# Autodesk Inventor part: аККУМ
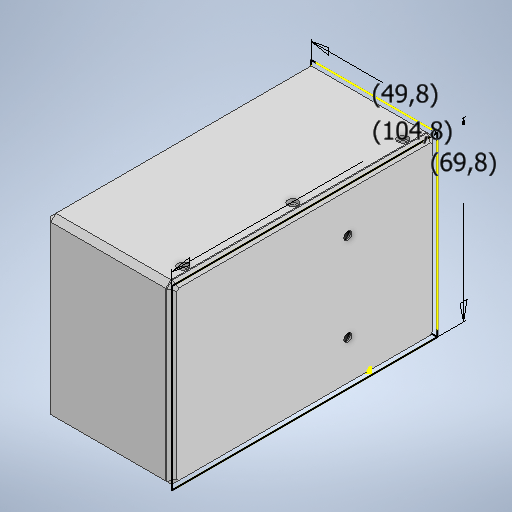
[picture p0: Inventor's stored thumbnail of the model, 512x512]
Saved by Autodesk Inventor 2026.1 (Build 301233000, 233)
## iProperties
Created: 2026-01
Part Number: аККУМ
Material: Типовые
Document SubType Name: Modeling
Designer: Yury Melnikov
Density: 1 g/cm^3
Appearance: По умолчанию
Author: Yury Melnikov
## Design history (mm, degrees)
sketch "Эскиз1"
  geometry: L1 (0, 0)-(65, 0); L2 (65, 0)-(65, 75); L3 (65, 75)-(0, 75); L4 (0, 75)-(0, 0); L5 (65, 0)-(0, 0); L6 (0, 0)-(0, -25); L7 (0, -25)-(65, -25); L8 (65, -25)-(65, 0); 1 further point
  constraints: 16 end point, 4 parallel, 2 horizontal, 2 perpendicular, 1 collinear
  dimensions: "d0" = 75 distance of L1.end L2.end; "d1" = 65 distance of L2.end L3.end; "d4" = 25 distance of L6.end L5.end
extrude "Выдавливание1" new body sketch "Эскиз1" distance "d2" = 45; taper "d3" = 0 deg
feature "Оболочка1" dims "d5" = 2.4
chamfer "Фаска1" distance "d9" = 2; stored, may be unused: second distance "d10" = 2, angle "d11" = 45 deg
sketch "Эскиз3"
  geometry: L1 (25, 63)-(25, 2) reference; L2 (23, 0)-(25, 2) reference; L3 (23, 0)-(-73, 0) reference; L4 (-75, 2)-(-73, 0) reference; L5 (-75, 2)-(-75, 63) reference; L6 (-73, 65)-(-75, 63) reference; L7 (-73, 65)-(23, 65) reference; L8 (25, 63)-(23, 65) reference; L9 (-75.4, -2.4)-(-77.4, -0.4) reference; L10 (-75.4, -2.4)-(25.4, -2.4) reference; L11 (27.4, -0.4)-(25.4, -2.4) reference; L12 (27.4, -0.4)-(27.4, 65.4) reference; L13 (25.4, 67.4)-(27.4, 65.4) reference; L14 (25.4, 67.4)-(-75.4, 67.4) reference; L15 (-77.4, 65.4)-(-75.4, 67.4) reference; L16 (-77.4, 65.4)-(-77.4, -0.4) reference; L17 (-72.917, 0.2)-(22.917, 0.2); L18 (22.917, 0.2)-(24.8, 2.083); L19 (24.8, 2.083)-(24.8, 62.917); L20 (24.8, 62.917)-(22.917, 64.8); L21 (22.917, 64.8)-(-72.917, 64.8); L22 (-72.917, 64.8)-(-74.8, 62.917); L23 (-74.8, 62.917)-(-74.8, 2.083); L24 (-74.8, 2.083)-(-72.917, 0.2); L25 (22.089, 2.2)-(-72.089, 2.2); L26 (-72.089, 2.2)-(-72.8, 2.911); L27 (-72.8, 2.911)-(-72.8, 62.089); L28 (-72.8, 62.089)-(-72.089, 62.8); L29 (-72.089, 62.8)-(22.089, 62.8); L30 (22.089, 62.8)-(22.8, 62.089); L31 (22.8, 62.089)-(22.8, 2.911); L32 (22.8, 2.911)-(22.089, 2.2); 1 further point
  constraints: 32 end point, 14 other
  dimensions: "d12" = 0.2 distance between parallel lines of L3 L17; "d13" = 2 distance between parallel lines of L17 L25
extrude "Выдавливание3" new body sketch "Эскиз3" distance "d14" = 5; taper "d15" = 0 deg
sketch "Эскиз4"
  geometry: L1 (25, 63)-(25, 2) reference; L2 (23, 0)-(25, 2) reference; L3 (23, 0)-(-73, 0) reference; L4 (-75, 2)-(-73, 0) reference; L5 (-75, 2)-(-75, 63) reference; L6 (-73, 65)-(-75, 63) reference; L7 (-73, 65)-(23, 65) reference; L8 (25, 63)-(23, 65) reference; L9 (-75.4, -2.4)-(-77.4, -0.4) reference; L10 (-75.4, -2.4)-(25.4, -2.4) reference; L11 (27.4, -0.4)-(25.4, -2.4) reference; L12 (27.4, -0.4)-(27.4, 65.4) reference; L13 (25.4, 67.4)-(27.4, 65.4) reference; L14 (25.4, 67.4)-(-75.4, 67.4) reference; L15 (-77.4, 65.4)-(-75.4, 67.4) reference; L16 (-77.4, 65.4)-(-77.4, -0.4) reference; 1 further point
extrude "Выдавливание4" join sketch "Эскиз4" distance "d16" = 2.4; taper "d17" = 0 deg
chamfer "Фаска2" distance "d18" = 2; stored, may be unused: second distance "d19" = 2, angle "d20" = 45 deg
chamfer "Фаска3" distance "d21" = 1.5; stored, may be unused: second distance "d22" = 2, angle "d23" = 45 deg
chamfer "Фаска4" distance "d24" = 0.5; stored, may be unused: second distance "d25" = 2, angle "d26" = 45 deg
sketch "Эскиз5"
  geometry: L1 (40.9, -98.317)-(40.9, -2.483) reference; L2 (45.4, -98.317)-(40.9, -98.317) reference; L3 (45.4, -2.483)-(45.4, -98.317) reference; L4 (45.4, -2.483)-(40.9, -2.483) reference; L5 (43.15, -93.817)-(43.15, -50.4); L6 (43.15, -50.4)-(43.15, -6.983); C1 r 0.75 at (43.15, -93.817); C2 r 0.75 at (43.15, -50.4); C3 r 0.75 at (43.15, -6.983); 3 further points
  constraints: 4 end point, 3 centre point, 2 collinear, 2 equal radius, 2 midpoint, 1 horizontal alignment, 1 point on line, 1 vertical
  dimensions: "d27" = 1.5 diameter of C2; "d28" = 4.5 distance from line of L2 L5.start
extrude "Выдавливание5" cut sketch "Эскиз5" distance "d29" = 75; taper "d30" = 0 deg
sketch "Эскиз8"
  geometry: L1 (-2.4, -2.4)-(98.4, -2.4) reference; L2 (-2.4, -2.4)-(72.6, -2.4); L3 (72.6, -2.4)-(72.6, 62.6); L4 (72.6, 62.6)-(-2.4, 62.6); L5 (-2.4, 62.6)-(-2.4, -2.4); L6 (74.6, -2.4)-(74.6, 62.6); L7 (72.6, -2.4)-(74.6, -2.4); L8 (72.6, 62.6)-(74.6, 62.6); L9 (74.6, 55.993)-(72.6, 55.993); L10 (72.6, 55.993)-(72.6, 64.22); L11 (72.6, 64.22)-(74.6, 64.22); L12 (74.6, 64.22)-(74.6, 55.993); 3 further points
  constraints: 22 end point, 5 parallel, 4 point on line, 3 horizontal, 2 perpendicular, 1 vertical
  dimensions: "d31" = 65 distance of L2.end L3.end; "d32" = 75 distance between parallel lines of L5 L3; "d33" = 2 distance between parallel lines of L6 L3
extrude "Выдавливание6" join sketch "Эскиз8" distance "d34" = 40; taper "d35" = 0 deg
chamfer "Фаска5" distance "d36" = 1; stored, may be unused: second distance "d37" = 2, angle "d38" = 45 deg
sketch "Эскиз9"
  geometry: L1 (0, 0)-(0, 65.8) reference; L2 (45.4, 0)-(0, 0) reference; L3 (15, 15)-(15, 50.8); C1 r 3 at (15, 15); C2 r 15 at (15, 15); C3 r 6.1 at (15, 50.8); 3 further points
  constraints: 3 centre point, 2 end point, 2 midpoint, 2 tangent, 1 coincident, 1 horizontal alignment, 1 vertical, 1 vertical alignment
  dimensions: "d39" = 6 diameter of C1; "d40" = 30 diameter of C2; "d41" = 12.2 diameter of C3
extrude "Выдавливание7" cut sketch "Эскиз9" distance "d42" = 3; taper "d43" = 0 deg
sketch "Эскиз10"
  geometry: L1 (40.4, -74)-(2.4, -74) reference; L2 (40.4, -74)-(40.4, -78) reference; L3 (2.4, -78)-(40.4, -78) reference; L4 (2.4, -98.4)-(2.4, -78) reference; L5 (45.4, -98.4)-(2.4, -98.4) reference; L6 (45.4, -2.4)-(45.4, -98.4) reference; L7 (2.4, -2.4)-(45.4, -2.4) reference; L8 (2.4, -74)-(2.4, -2.4) reference; L9 (31.65, -83.95)-(16.15, -83.95); L10 (16.15, -83.95)-(16.15, -92.45); L11 (16.15, -92.45)-(31.65, -92.45); L12 (31.65, -92.45)-(31.65, -83.95); C1 r 0.75 at (43.15, -93.817) reference; C2 r 0.75 at (43.15, -50.4) reference; C3 r 0.75 at (43.15, -6.983) reference; 5 further points
  constraints: 8 end point, 4 midpoint, 2 parallel, 1 horizontal, 1 horizontal alignment, 1 perpendicular, 1 vertical alignment
  dimensions: "d44" = 15.5 distance of L11.end L10.end; "d45" = 8.5 distance of L10.end L9.end
extrude "Выдавливание8" cut sketch "Эскиз10" distance "d46" = 3; taper "d47" = 0 deg
chamfer "Фаска6" distance "d48" = 0.7; stored, may be unused: second distance "d49" = 2, angle "d50" = 45 deg
chamfer "Фаска7" distance "d51" = 0.5; stored, may be unused: second distance "d52" = 2, angle "d53" = 45 deg
sketch "Эскиз11"
  geometry: C1 r 0.75 at (43.15, -6.983) reference; C2 r 0.75 at (43.15, -50.4) reference; C3 r 0.75 at (43.15, -93.817) reference; C4 r 2 at (43.15, -6.983); C5 r 2 at (43.15, -50.4); C6 r 2 at (43.15, -93.817); 1 further point
  constraints: 3 centre point, 2 equal radius
  dimensions: "d54" = 4 diameter of C4
extrude "Выдавливание9" cut sketch "Эскиз11" distance "d55" = 1.4; taper "d56" = 0 deg
chamfer "Фаска8" distance "d57" = 0.5; stored, may be unused: second distance "d58" = 2, angle "d59" = 45 deg
node "РабПлоскость2"
mirror "Зеркальное отражение1"
node "РабПлоскость3"
sketch "Эскиз12"
  geometry: L1 (2, 61)-(2, 0) reference; L2 (2, 0)-(2, 61) reference; L3 (2, 9.6)-(2, 15.6) reference; L4 (2, 42.3)-(2, 54.5) reference; L5 (2, 49)-(-4.5, 49); L6 (-4.5, 49)-(-4.5, 42); L7 (-4.5, 42)-(-2.5, 42); L8 (-2.5, 42)-(-2.5, 47); L9 (-2.5, 47)-(2, 47); L10 (-2.5, 47)-(-2.5, 49); L11 (2, 30.5)-(16.292, 30.5); L12 (2, 18.7)-(2, 6.5); L13 (2, 12)-(-4.5, 12); L14 (-4.5, 12)-(-4.5, 19); L15 (-4.5, 19)-(-2.5, 19); L16 (-2.5, 19)-(-2.5, 14); L17 (-2.5, 14)-(2, 14); L18 (-2.5, 14)-(-2.5, 12); 6 further points
  constraints: 28 end point, 9 symmetric about line, 8 point on line, 3 horizontal, 3 perpendicular, 2 midpoint, 1 vertical
  dimensions: "d62" = 5 distance of L7.end L8.end; "d63" = 2 distance of L6.end L7.end; "d64" = 4.5 distance of L8.end L9.end; "d65" = 33 distance from line of L17 point (-0.25, 47)
extrude "Выдавливание10" join sketch "Эскиз12" distance "d66" = 6; taper "d67" = 0 deg
sketch "Эскиз13"
  geometry: L1 (37, 16.4)-(37, 21.4) reference; L2 (37, 21.4)-(31, 21.4) reference; L3 (31, 16.4)-(31, 21.4) reference; L4 (37, 16.4)-(31, 16.4) reference; L5 (37, 44.4)-(37, 49.4) reference; L6 (37, 49.4)-(31, 49.4) reference; L7 (31, 44.4)-(31, 49.4) reference; L8 (37, 44.4)-(31, 44.4) reference; L9 (27.35, 16.65)-(40.65, 16.65); L10 (40.65, 16.65)-(40.65, 49.15); L11 (40.65, 49.15)-(27.35, 49.15); L12 (27.35, 49.15)-(27.35, 16.65); L13 (31, 21.4)-(31, 44.4); C1 r 1.65 at (30.35, 41.15); C2 r 1.65 at (30.35, 36.15); C3 r 1.65 at (30.35, 31.15); C4 r 1.65 at (30.35, 26.15); C5 r 2.1 at (35.65, 41.65); 5 further points
  constraints: 10 end point, 5 centre point, 4 midpoint, 2 parallel, 2 vertical, 1 horizontal, 1 horizontal alignment, 1 perpendicular, 1 vertical alignment, 6 other
  dimensions: "d68" = 32.5 distance of L11.end L9.start; "d69" = 13.3 distance of L9.start L9.end; "d70" = 3 horizontal distance of C1.centre L11.end; "d71" = 8 vertical distance of L11.end C1.centre; "d72" = 3.3 diameter of C1; "d75" = 5 distance of C1.centre C2.centre; "d80" = 4.2 diameter of C5; "d81" = 7.5 vertical distance of L10.end C5.centre; "d82" = 5 distance from line of L10 C5.centre
extrude "Выдавливание11" cut sketch "Эскиз13" distance "d83" = 6; taper "d84" = 0 deg
chamfer "Фаска9" distance "d85" = 0.5; stored, may be unused: second distance "d86" = 2, angle "d87" = 45 deg
chamfer "Фаска10" distance "d88" = 3; stored, may be unused: second distance "d89" = 2, angle "d90" = 45 deg
sketch "Эскиз14"
  geometry: L1 (-77.4, 65.4)-(-77.4, -0.4) reference; L2 (-7.94, 49.9)-(-7.94, 15.1); L3 (25.4, 64.572)-(25.4, 0.428) reference; C1 r 1.6 at (-7.94, 49.9); C2 r 1.6 at (-7.94, 15.1); 3 further points
  constraints: 2 centre point, 2 end point, 2 midpoint, 1 equal radius, 1 horizontal alignment, 1 vertical, 1 vertical alignment
  dimensions: "d91" = 69.46 distance from line of L1 L2.start; "d92" = 38 dimension on C1 C2; "d93" = 3.2 diameter of C1
extrude "Выдавливание12" cut sketch "Эскиз14" distance "d94" = 10; taper "d95" = 0 deg
chamfer "Фаска11" distance "d96" = 1.8; stored, may be unused: second distance "d97" = 2, angle "d98" = 45 deg
sketch "Эскиз15"
  geometry: L1 (-77.4, 67.4)-(27.4, 67.4); L2 (27.4, 67.4)-(27.4, -2.4); L3 (27.4, -2.4)-(-77.4, -2.4); L4 (-77.4, -2.4)-(-77.4, 67.4); L5 (25.4, 67.4)-(-75.4, 67.4) reference; L6 (-77.4, 65.4)-(-77.4, -0.4) reference; L7 (-75.4, -2.4)-(25.4, -2.4) reference; L8 (27.4, -0.4)-(27.4, 65.4) reference; 1 further point
  constraints: 8 end point, 4 collinear, 2 parallel, 1 horizontal, 1 perpendicular
  dimensions: "d99" = 104.8 distance of L1.start L1.end (derived); "d100" = 69.8 distance of L1.end L2.end (derived)
sketch "Эскиз16"
  geometry: L1 (-2.4, -2)-(47.4, -2); L2 (47.4, -2)-(47.4, 67.8); L3 (47.4, 67.8)-(-2.4, 67.8); L4 (-2.4, 67.8)-(-2.4, -2); L5 (45.4, 67.8)-(0, 67.8) reference; L6 (47.4, 0)-(47.4, 65.8) reference; L7 (-2.4, 64.972)-(-2.4, 0.828) reference; L8 (0, -2)-(45.4, -2) reference; 1 further point
  constraints: 8 end point, 4 collinear, 2 parallel, 1 horizontal, 1 perpendicular
  dimensions: "d101" = 49.8 distance of L2.end L3.end (derived)
node "Твердое тело1"
node "Спроецированная петля2"
node "Твердое тело2"
node "Спроецированная петля3"
node "Спроецированная петля4"
node "Спроецированная петля5"
node "Спроецированная петля6"
node "Спроецированная петля7"
node "Спроецированная петля8"
node "Эскиз — прямоугольный массив1" dims "d75" = 5, "d78" = 10
other parameters: "d60" = 8
